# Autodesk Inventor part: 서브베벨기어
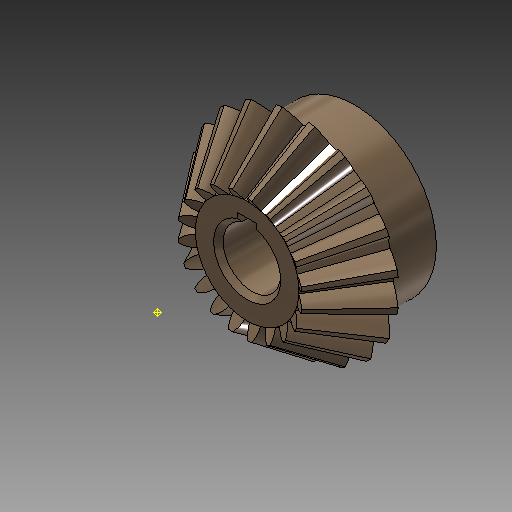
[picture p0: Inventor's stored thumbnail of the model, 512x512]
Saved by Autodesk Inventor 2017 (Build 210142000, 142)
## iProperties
Created: 2018-09
Part Number: 서브베벨기어
Material: 강철, 탄소
Document SubType Name: Modeling
Categories: <?xml version="1.0" encoding="UTF-16"?> <MemberInstance><Categories><FamilyTemplate><FamilyTemplateParameter ValueType="xs:double" Id="1" ObjectReferenceKey="da
Mass: 135.037 g
Surface Area: 63.6494 cm^2
Volume: 17.1585 cm^3
Density: 7.87 g/cm^3
Appearance: 얼룩무늬
CustomPartVersion: 1
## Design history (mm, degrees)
node "맨 위 점"
node "메쉬 평면2"
sketch "톱니 본체 스케치"
  geometry: L1 (0, 0)-(18.003, -31.331); L2 (18.003, -31.331)-(21.664, -28.891); L3 (21.664, -28.891)-(0, 0); L4 (20, -30)-(0, 0); L5 (10.813, -18.818)-(13.012, -17.352); L6 (18.003, -31.331)-(10.813, -18.818); L7 (21.664, -28.891)-(13.012, -17.352); L8 (0, -39.387)-(0, 6.564) reference; L9 (0, -30)-(21.664, -30)
  constraints: 16 end point, 4 point on line, 3 perpendicular, 2 collinear, 1 horizontal alignment, 1 vertical alignment
  dimensions: "d0" = 40 diameter of L4.start L8 (= da_de); "d1" = 36.00616 diameter of L1.end L8 (= da_dfe); "d2" = 43.3282 diameter of L2.end L8 (= da_dae); "d3" = 14.4 distance between parallel lines of L2 L5 (= da_b); "d4" = 28.8906 vertical distance of L2.end L1.start (= da_ve)
revolve "톱니 본체" sketch "톱니 본체 스케치" stored, may be unused: angle "d5" = 90 deg
node "시작점"
node "톱니 평면"
sketch "시작 스케치"
  geometry: L1 (0, -23.505)-(0, 10.645) reference; L2 (-0.834, -2.928)-(0.834, -2.928); A1 r 8.898 centre (-9.698, -3.713) between (-0.834, -2.928) and (-3.903, 3.04); A2 r 8.898 centre (9.698, -3.713) between (3.903, 3.04) and (0.834, -2.928); A3 r 27.357 centre (0, -24.037) between (3.903, 3.04) and (-3.903, 3.04); 1 further point
  constraints: 6 point on circle, 3 centre point, 3 symmetric about line, 2 end point, 1 coincident, 1 perpendicular, 1 other
  dimensions: "d7" = 8.89846 radius of A1 (= fd_rr); "d8" = 9.69794 horizontal distance of point (0, -24.037) A1.centre (= fd_x); "d9" = 20.32439 vertical distance of point (0, -24.037) A1.centre (= fd_y); "d57" = 27.35701 radius of A3 (= 0.5 x fd_dva + 0.3 x da_he); "d58" = 21.10901 distance from line of A3.centre L2 (= 0.5 x fd_dva - 1.12 x da_he)
node "끝점"
  node "끝 평면"
sketch "3D 스케치 오른쪽"
  node "Helical Curve Right" dims "d65" = 229.90621 (computed from da_dm, da_delta, da_beta), "d66" = 31.5, "d67" = 40 (= da_de), "d68" = -5.88003 (= -da_delta), "d69" = 12.16458 (computed from fd_loft, da_delta)
node "끝 평면 오른쪽"
sketch "끝 스케치 오른쪽"
  geometry: L1 (0, -22.649)-(0, 12.15) reference; L2 (-0.497, -1.72)-(0.497, -1.72); A1 r 5.299 centre (-5.775, -2.187) between (-0.497, -1.72) and (-2.324, 1.834); A2 r 5.299 centre (5.775, -2.187) between (2.324, 1.834) and (0.497, -1.72); A3 r 16.291 centre (0, -14.29) between (2.324, 1.834) and (-2.324, 1.834); 1 further point
  constraints: 6 point on circle, 3 centre point, 3 symmetric about line, 2 end point, 1 coincident, 1 perpendicular, 1 other
  dimensions: "d70" = 5.77526 horizontal distance of A3.centre A1.centre (computed from fd_x, fd_ratio); "d71" = 12.10346 vertical distance of point (0, -14.29) A1.centre (computed from fd_y, fd_ratio); "d72" = 5.29916 radius of A1 (computed from fd_rr, fd_ratio); "d73" = 12.57071 distance from line of point (0, -14.29) L2 (computed from d58, fd_ratio); "d74" = 16.29149 radius of A3 (computed from d57, fd_ratio)
feature "로프트 오른쪽" sketch "끝 스케치 오른쪽" dims "d75" = 0, "d77" = 0, "d79" = 0, "d80" = 90 deg, "d85" = 20, "d92" = 90 deg, "d93" = 90 deg, "da_teethtype" = 0 [user parameter]
sketch "3D 스케치 왼쪽"
  node "Helical Curve Left" dims "d26" = 229.90621 (computed from da_dm, da_delta, da_beta), "d27" = 12.16458 (computed from fd_loft, da_delta), "d28" = 40 (= da_de), "d29" = -5.88003 (= -da_delta)
node "끝 평면 왼쪽"
sketch "끝 스케치 왼쪽" dims "d56" = 10.82768 (derived)
  geometry: L1 (0, -35.087)-(0, 18.089) reference; L2 (-0.497, -1.716)-(0.497, -1.716); A1 r 5.299 centre (-5.775, -2.183) between (-0.497, -1.716) and (-2.324, 1.838); A2 r 5.299 centre (5.775, -2.183) between (2.324, 1.838) and (0.497, -1.716); A3 r 16.291 centre (0, -14.287) between (2.324, 1.838) and (-2.324, 1.838); 2 further points; 1 other entity
  constraints: 6 point on circle, 3 centre point, 3 symmetric about line, 2 end point, 1 coincident, 2 other
  dimensions: "d30" = 5.29916 radius of A1 (computed from fd_rr, fd_ratio); "d31" = 5.77526 horizontal distance of point (0, -14.287) A1.centre (computed from fd_x, fd_ratio); "d32" = 12.10346 vertical distance of A1.centre point (0, -14.287) (computed from fd_y, fd_ratio); "d61" = 16.29149 radius of A3 (computed from d57, fd_ratio); "d62" = 12.57071 distance from line of point (0, -14.287) L2 (computed from d58, fd_ratio)
feature "로프트 왼쪽" sketch "끝 스케치 왼쪽" dims "d35" = 0, "d37" = 0, "d39" = 0, "d40" = 90 deg, "d84" = 10, "d90" = 90 deg, "d91" = 90 deg, "da_teethtype" = 0 [user parameter]
sketch "본체 스케치"
  geometry: L1 (0, -35.038)-(0, -19.531) reference; L2 (18.003, -31.331)-(10.813, -18.818) reference; L3 (10.813, -18.818)-(0, -18.818); L4 (18.003, -31.331)-(0, -31.331)
  constraints: 4 end point, 2 perpendicular, 2 point on line
revolve "본체 고정" sketch "본체 스케치" stored, may be unused: angle "d46" = 90 deg
feature "피치 지름" dims angle "d47" = 90 deg
sketch "스케치8"
  geometry: C1 r 17 at (0, 0); 1 further point
  constraints: 1 centre point, 1 coincident
  dimensions: "d94" = 34 diameter of C1
extrude "돌출1" join sketch "스케치8" distance "d95" = 10; taper "d96" = 0 deg
sketch "스케치9"
  geometry: 1 further point
hole "구멍1" sketch "스케치9" at (0, 0) diameter "d97" = 12; stored, may be unused: countersink angle "d101" = 90 deg, drill point angle "d103" = 118 deg; dims "d98" = 6, "d99" = 4, "d100" = 2, "d102" = 8
sketch "스케치10"
  geometry: 1 further point
sketch "스케치11"
  geometry: 1 further point
sketch "스케치12"
  geometry: L1 (-2, 5.657)-(-2, 7.8); L2 (-2, 7.8)-(2, 7.8); L3 (2, 7.8)-(2, 5.657); A1 r 6 centre (0, 0) between (-2, 5.657) and (2, 5.657) reference; 1 further point
  constraints: 6 end point, 2 parallel, 2 point on circle, 1 perpendicular, 1 vertical
  dimensions: "d104" = 4 distance of L1.end L2.end; "d105" = 13.8 dimension on A1 L2
extrude "돌출2" cut sketch "스케치12" stored distance "d106" = 7; taper "d107" = 0 deg
chamfer "모따기1" distance "d108" = 1; stored, may be unused: second distance "d109" = 2, angle "d110" = 45 deg
body "Solid1"
feature "로프트" dims "d17" = 0, "d18" = 90 deg, "d19" = 0, "d20" = 90 deg, "d89" = 0, "da_teethtype" = 0 [user parameter]
pattern_circular "원형 패턴" dims angle "d22" = 360 deg, "d88" = 0, "da_teethtype" = 0 [user parameter]
pattern_circular "원형 패턴 오른쪽" dims angle "d82" = 360 deg, "da_teethtype" = 0 [user parameter]
pattern_circular "원형 패턴 왼쪽" dims angle "d42" = 360 deg, "da_teethtype" = 0 [user parameter]
sketch "끝 스케치"
  geometry: L1 (0, -15.359)-(0, 6.983) reference; L2 (-0.497, -1.72)-(0.497, -1.72); A1 r 5.299 centre (-5.775, -2.187) between (-0.497, -1.72) and (-2.324, 1.834); A2 r 5.299 centre (5.775, -2.187) between (2.324, 1.834) and (0.497, -1.72); A3 r 16.291 centre (0, -14.29) between (2.324, 1.834) and (-2.324, 1.834); 1 further point
  constraints: 6 point on circle, 3 centre point, 3 symmetric about line, 2 end point, 1 coincident, 1 other
  dimensions: "d12" = 5.29916 radius of A1 (computed from fd_rr, fd_ratio); "d15" = 5.77526 horizontal distance of A1.centre point (0, -14.29) (computed from fd_x, fd_ratio); "d16" = 12.10346 vertical distance of A1.centre point (0, -14.29) (computed from fd_y, fd_ratio); "d59" = 16.29149 radius of A3 (computed from d57, fd_ratio); "d60" = 12.57071 distance from line of A3.centre L2 (computed from d58, fd_ratio)
sketch "Sketch6"
  geometry: L1 (20, -30)-(0, 0) reference; L2 (0, -37.8)-(0, 6.3) reference
body "Srf1"
other parameters: "da_b" = 14.4 [user parameter; used in 2 equation terms], "da_de" = 40 [user parameter; used in 4 equation terms], "da_dae" = 43.3282 [user parameter; used in 2 equation terms], "da_dfe" = 36.00616 [user parameter; used in 1 equation term], "da_le" = 36.05551 [user parameter; used in 1 equation term], "da_omega" = 90 deg [user parameter; used in 1 equation term], "da_beta" = 0 [user parameter; used in 2 equation terms], "da_delta" = 5.88003 [user parameter; used in 8 equation terms], "da_alpha" = 20 deg [user parameter; used in 2 equation terms], "da_he" = 4.4 [user parameter; used in 4 equation terms], "da_ve" = 28.8906 [user parameter; used in 1 equation term], "fd_dv" = 48.07402 (computed from da_de, da_delta) [user parameter; used in 1 equation term], "fd_dva" = 52.07402 (computed from da_dae, da_delta) [user parameter; used in 3 equation terms], "fd_dvb" = 45.1748 (computed from fd_dv, da_alpha) [user parameter; used in 2 equation terms], "da_zv" = 240.37008 [user parameter; used in 1 equation term], "fd_loft" = 14.62 (= da_b + 0.05 x da_he) [user parameter; used in 4 equation terms], "fd_ratio" = 5.95514 (computed from da_le, fd_loft) [user parameter; used in 15 equation terms], "fd_rr" = 8.89846 (computed from fd_dd, fd_dvb) [user parameter; used in 6 equation terms], "fd_angle" = 0.66075 (computed from da_zv) [user parameter; used in 4 equation terms], "fd_x1" = 1.58709 (computed from da_dvw, fd_angle) [user parameter; used in 1 equation term], "fd_y1" = 23.98456 (computed from da_dvw, fd_angle) [user parameter; used in 1 equation term], "fd_x2" = 8.11084 (computed from fd_rr, fd_angle2, fd_angle) [user parameter; used in 1 equation term], "fd_y2" = 3.66016 (computed from fd_rr, fd_angle2, fd_angle) [user parameter; used in 1 equation term], "fd_x" = 9.69794 (= fd_x1 + fd_x2) [user parameter; used in 4 equation terms], "fd_y" = 20.32439 (= fd_y1 - fd_y2) [user parameter; used in 4 equation terms], "fd_angle2" = 3.57832 (computed from fd_dvb, fd_dd, da_alpha) [user parameter; used in 2 equation terms], "fd_dd" = 48.55402 (= fd_dva - 0.8 x da_he) [user parameter; used in 2 equation terms], "da_dvw" = 48.07402 [user parameter; used in 2 equation terms], "d11" = 14.62 (= fd_loft), "da_dm" = 32.01232 [user parameter; used in 2 equation terms], "da_x" = 0 [user parameter], "da_m" = 2 [user parameter], "d48" = 0, "d49" = 0, "d50" = 90 deg (= da_omega), "d51" = 9 deg (computed from da_z), "d52" = 0, "d53" = 0, "d54" = 0
